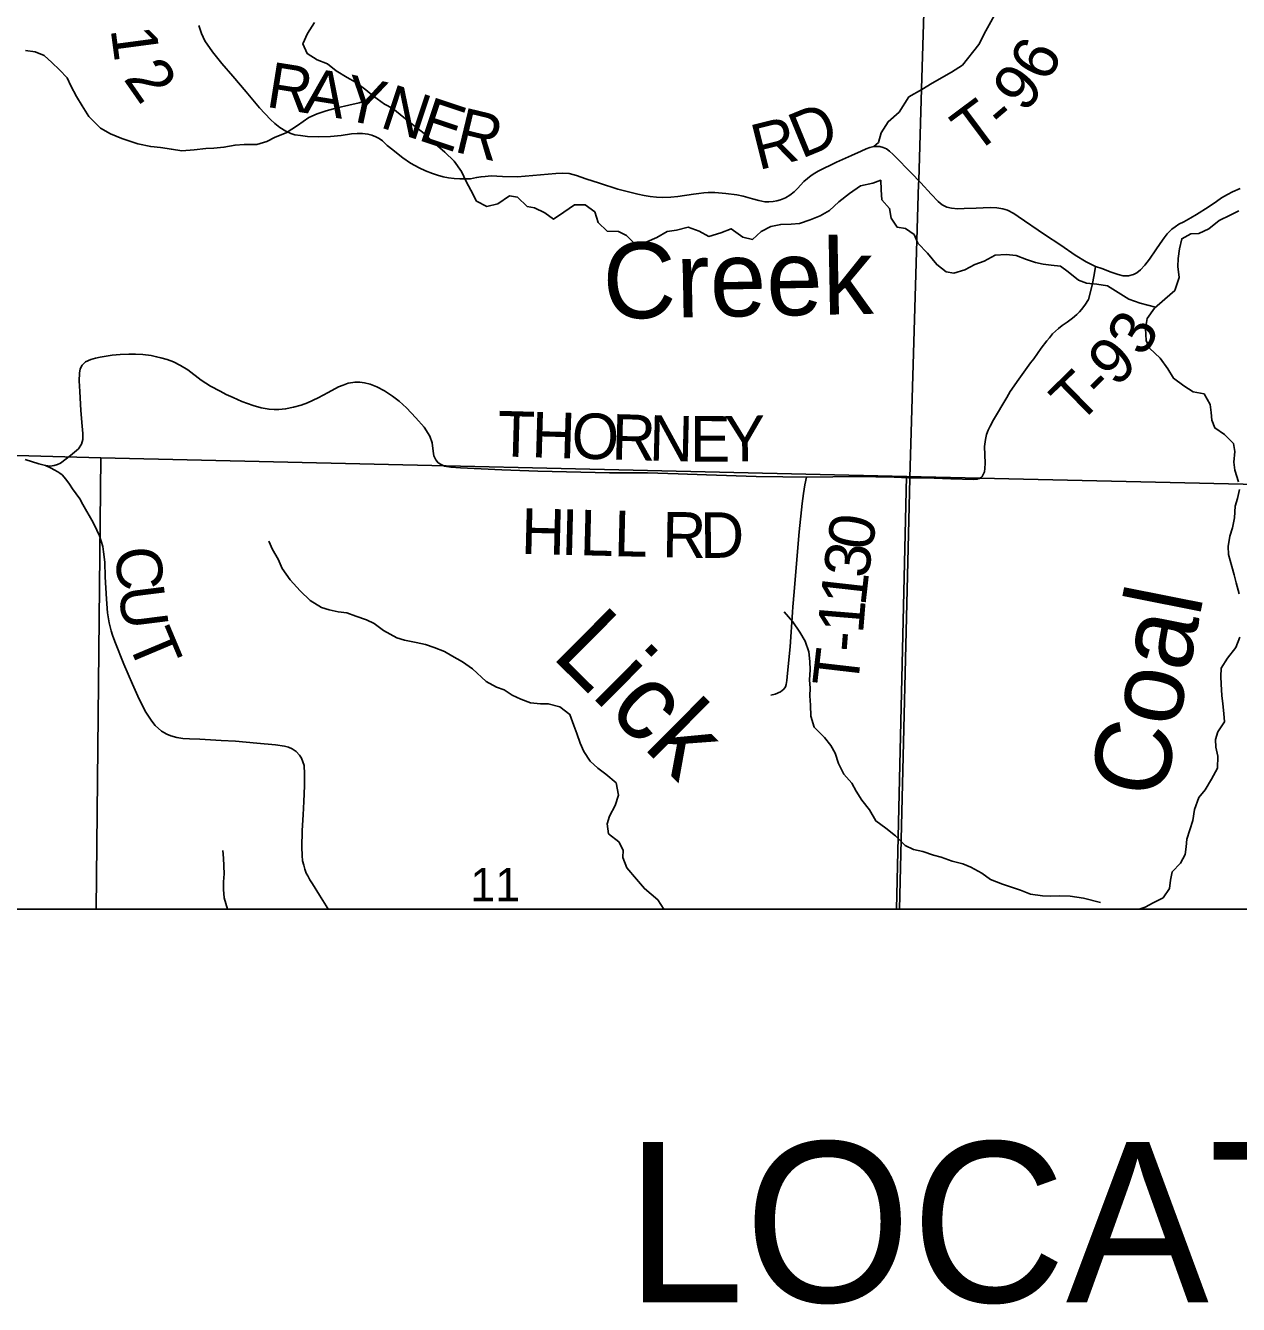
# Model space of a CAD drawing. Extents: x 0 to 34, y 0 to 22.
# Drawn here: x 2.631 to 4.145, y 14.08 to 15.676 of the extents above; entities that cross this region are included whole.
import ezdxf

# ---------------------------------------------------------------- set-up
doc = ezdxf.new("R2010")
doc.units = 0
for name, color, linetype in [('GM_X_Corporation', 7, 'Continuous'), ('GM_X_County_Road', 7, 'Continuous'), ('GM_X_County_Road_Text', 7, 'Continuous'), ('GM_X_Minor_River', 7, 'Continuous'), ('GM_X_Minor_River_Text', 7, 'Continuous'), ('GM_X_Section_Text', 7, 'Continuous'), ('GM_X_Township_Road', 7, 'Continuous'), ('GM_X_Township_Road_Text', 7, 'Continuous'), ('SH_Text', 7, 'Continuous')]:
    doc.layers.add(name, color=color, linetype=linetype)

msp = doc.modelspace()

# ---------------------------------------------------------------- linework, layer by layer
at = {"layer": 'GM_X_Corporation'}
for points in [[(4.1576, 16.1007), (3.7652, 16.1115), (2.3935, 16.1523), (2.3716, 16.1532), (1.6311, 16.1731), (1.6311, 14.5734), (8.4311, 14.5734)], [(4.1576, 16.1007), (3.7652, 16.1115), (3.7495, 15.5967), (3.7461, 15.4826), (3.7459, 15.4785), (3.7348, 15.1121), (3.7347, 15.1105), (3.7221, 14.5734), (8.4311, 14.5734)]]:
    msp.add_lwpolyline(points, dxfattribs=at)
for points in [[(1.6311, 16.1731), (1.6311, 14.5734), (3.7221, 14.5734), (3.7347, 15.1105), (3.7348, 15.1121), (3.7459, 15.4785), (3.7461, 15.4826), (3.7495, 15.5967), (3.7652, 16.1115), (2.3935, 16.1523), (2.3716, 16.1532)], [(1.7122, 14.5734), (2.7191, 14.5734), (2.725, 15.1366), (1.7214, 15.1643)], [(2.7191, 14.5734), (3.7181, 14.5734), (3.7309, 15.1133), (2.725, 15.1366)], [(3.7181, 14.5734), (4.7275, 14.5734), (4.7356, 15.0283), (4.7361, 15.0901), (3.7309, 15.1133)]]:
    msp.add_lwpolyline(points, close=True, dxfattribs=at)
at = {"layer": 'GM_X_County_Road'}
for points in [[(2.8476, 15.676), (2.8508, 15.6658), (2.8549, 15.6566), (2.8644, 15.6432), (2.8761, 15.6287), (2.8897, 15.6126), (2.9066, 15.5932), (2.9231, 15.5733), (2.9368, 15.5588), (2.9423, 15.5537), (2.9485, 15.5485), (2.9561, 15.544), (2.9622, 15.5411), (2.9671, 15.5397), (2.9745, 15.5386), (2.983, 15.5376), (2.9973, 15.5371), (3.0117, 15.5375), (3.0252, 15.5388), (3.0381, 15.5406), (3.0449, 15.5411), (3.0518, 15.5413), (3.0585, 15.5405), (3.0634, 15.5392), (3.0683, 15.5371), (3.0726, 15.5348), (3.0766, 15.532), (3.0827, 15.5264), (3.0897, 15.5206), (3.0961, 15.5153), (3.1022, 15.5107), (3.1118, 15.5043), (3.1226, 15.4985), (3.1305, 15.4946), (3.1389, 15.4913), (3.1452, 15.4892), (3.1523, 15.4873), (3.1592, 15.486), (3.1661, 15.485), (3.1734, 15.4845), (3.1798, 15.4845), (3.1865, 15.4848), (3.1941, 15.4862), (3.1997, 15.4873), (3.205, 15.4877), (3.2124, 15.4882), (3.2193, 15.488), (3.2265, 15.4876), (3.245, 15.4871), (3.2929, 15.4914), (3.3011, 15.4917), (3.3097, 15.4912), (3.3187, 15.4887), (3.3303, 15.4847), (3.3477, 15.479), (3.3705, 15.4719), (3.3822, 15.4688), (3.3954, 15.4656), (3.4032, 15.464), (3.4108, 15.4627), (3.4185, 15.4616), (3.4267, 15.4614), (3.4364, 15.4616), (3.4453, 15.4624), (3.4648, 15.4655), (3.4714, 15.4665), (3.4777, 15.4671), (3.4833, 15.4675), (3.4917, 15.4677), (3.5054, 15.4665), (3.519, 15.4646), (3.5269, 15.4628), (3.5386, 15.4596), (3.5463, 15.4576), (3.554, 15.456), (3.5588, 15.456), (3.5645, 15.4564), (3.5687, 15.4572), (3.5733, 15.4584), (3.5795, 15.461), (3.5852, 15.4644), (3.5904, 15.4684), (3.5948, 15.4725), (3.6027, 15.4811), (3.6118, 15.4887), (3.6163, 15.4917), (3.6206, 15.4941), (3.6434, 15.5052), (3.662, 15.5139), (3.674, 15.5193), (3.6804, 15.5221)], [(3.6804, 15.5221), (3.685, 15.5238), (3.6899, 15.5249), (3.6976, 15.5249), (3.7016, 15.5239), (3.7059, 15.5219), (3.7097, 15.5192), (3.7141, 15.5151), (3.7386, 15.4899), (3.7463, 15.4821), (3.7487, 15.4796), (3.7615, 15.4653), (3.7701, 15.4562), (3.7753, 15.4523), (3.7811, 15.4494), (3.787, 15.4478), (3.7948, 15.4472), (3.8026, 15.4474), (3.8176, 15.4481), (3.8353, 15.4488), (3.8435, 15.4483), (3.8511, 15.4471), (3.8567, 15.4454), (3.8645, 15.4413), (3.8703, 15.4374), (3.9031, 15.4152), (3.9234, 15.4017), (3.9412, 15.3893), (3.9551, 15.3811), (3.9668, 15.3752), (3.9746, 15.3726), (3.9864, 15.368), (3.9951, 15.3652), (4.0013, 15.3637), (4.0079, 15.3636), (4.0142, 15.3651), (4.0184, 15.3675), (4.023, 15.371), (4.0284, 15.3769), (4.0339, 15.3844), (4.0421, 15.3959), (4.0475, 15.4039), (4.0524, 15.4109), (4.0563, 15.4158), (4.0621, 15.4216), (4.066, 15.4247), (4.0708, 15.4279), (4.0767, 15.4311), (4.0855, 15.4358), (4.0929, 15.4403), (4.1072, 15.4491), (4.1178, 15.4565), (4.124, 15.4608), (4.1314, 15.4652), (4.1377, 15.4684), (4.1474, 15.4727)]]:
    msp.add_lwpolyline(points, dxfattribs=at)
at = {"layer": 'GM_X_Minor_River'}
for points in [[(4.0414, 15.3243), (4.0224, 15.3296), (4.0083, 15.3345), (3.9818, 15.3511), (3.9685, 15.3533), (3.9553, 15.3544), (3.9454, 15.3582), (3.9325, 15.3684), (3.923, 15.3755), (3.9113, 15.377), (3.9014, 15.3781), (3.8916, 15.3804), (3.8806, 15.3841), (3.8677, 15.389), (3.8552, 15.3901), (3.8416, 15.3893), (3.8276, 15.382), (3.8162, 15.3778), (3.8034, 15.371), (3.7898, 15.3671), (3.7803, 15.3686), (3.7685, 15.3777), (3.7571, 15.3917), (3.745, 15.4045), (3.7404, 15.4151), (3.7294, 15.4227), (3.7192, 15.4241), (3.7116, 15.4355), (3.7096, 15.4476), (3.7001, 15.4582), (3.6993, 15.4707), (3.6985, 15.4828), (3.6887, 15.479), (3.6732, 15.4759), (3.6596, 15.4664), (3.6464, 15.4561), (3.6347, 15.4451), (3.6229, 15.4386), (3.6105, 15.4336), (3.5972, 15.429), (3.5866, 15.4282), (3.5738, 15.4278), (3.5616, 15.4251), (3.5495, 15.419), (3.5386, 15.4091), (3.5265, 15.4117), (3.5117, 15.4223), (3.4988, 15.4173), (3.4841, 15.4127), (3.4719, 15.4191), (3.4583, 15.4244), (3.4435, 15.4205), (3.4318, 15.419), (3.4193, 15.4114), (3.4065, 15.406), (3.3921, 15.4029), (3.3811, 15.4139), (3.3712, 15.4188), (3.3572, 15.4195), (3.3458, 15.4301), (3.3416, 15.4433), (3.3295, 15.452), (3.3162, 15.4523), (3.303, 15.4432), (3.2901, 15.4344), (3.2791, 15.442), (3.2666, 15.4484), (3.2571, 15.4502), (3.245, 15.4616), (3.2351, 15.4634), (3.2208, 15.4532), (3.2068, 15.4501), (3.1939, 15.4569), (3.187, 15.4705), (3.181, 15.4811), (3.1752, 15.4936), (3.1661, 15.5068), (3.1543, 15.5178), (3.1426, 15.5283), (3.1285, 15.5412), (3.1156, 15.551), (3.1031, 15.5612), (3.0894, 15.5725), (3.0792, 15.5778), (3.0655, 15.5876), (3.0557, 15.5955), (3.0431, 15.6053), (3.0325, 15.611), (3.0189, 15.6193), (3.0079, 15.6283), (2.995, 15.6332), (2.9828, 15.6408), (2.9771, 15.6529), (2.9831, 15.6658), (2.9918, 15.6798)], [(3.0673, 15.5863), (3.0474, 15.5796), (3.0345, 15.5765), (3.0201, 15.5734), (3.0065, 15.5696), (2.9952, 15.5657), (2.9846, 15.5612), (2.9706, 15.5513), (2.9566, 15.5421), (2.9426, 15.5364), (2.9324, 15.531), (2.9199, 15.5276), (2.904, 15.5275), (2.8927, 15.5267), (2.8787, 15.524), (2.8662, 15.5228), (2.856, 15.5224), (2.8416, 15.5209), (2.8264, 15.5197), (2.8132, 15.5215), (2.7995, 15.5238), (2.7874, 15.5248), (2.7711, 15.5282), (2.7514, 15.535), (2.737, 15.5406), (2.7245, 15.5478), (2.7101, 15.5625), (2.7017, 15.5757), (2.6948, 15.5875), (2.6876, 15.6007), (2.683, 15.6106), (2.6735, 15.6208), (2.6641, 15.6298), (2.6542, 15.6385), (2.6432, 15.643), (2.6311, 15.6449)], [(4.1454, 15.4445), (4.1349, 15.4392), (4.1209, 15.4327), (4.108, 15.4224), (4.0955, 15.4163), (4.0857, 15.4159), (4.0744, 15.4098), (4.0714, 15.3973), (4.0699, 15.3851), (4.0695, 15.3753), (4.0711, 15.3616), (4.0655, 15.3453), (4.053, 15.3343), (4.0402, 15.3232), (4.0311, 15.3103), (4.0289, 15.2978), (4.0297, 15.283), (4.0339, 15.2732), (4.0472, 15.2607), (4.0571, 15.2474), (4.0639, 15.2357), (4.0768, 15.2263), (4.0886, 15.2187), (4.1022, 15.2165), (4.1098, 15.2029), (4.111, 15.193), (4.1118, 15.1836), (4.1156, 15.1737), (4.1277, 15.1654), (4.1387, 15.1544), (4.1407, 15.1442), (4.1392, 15.1309), (4.1404, 15.1211), (4.1453, 15.1067)], [(4.1465, 15.0968), (4.1439, 15.0858), (4.1409, 15.0763), (4.1402, 15.0615), (4.1375, 15.049), (4.1345, 15.0388), (4.1323, 15.0259), (4.1327, 15.016), (4.1369, 15.0009), (4.1396, 14.9903), (4.1423, 14.9804), (4.1461, 14.9668)], [(3.4277, 14.5734), (3.4203, 14.585), (3.4036, 14.599), (3.3937, 14.6107), (3.3816, 14.6247), (3.3766, 14.6376), (3.377, 14.6471), (3.3716, 14.6573), (3.3587, 14.6675), (3.3572, 14.6796), (3.3602, 14.6895), (3.3669, 14.7028), (3.3714, 14.7157), (3.3684, 14.7309), (3.3555, 14.7418), (3.3456, 14.7494), (3.3357, 14.7581), (3.3281, 14.7702), (3.3235, 14.7804), (3.3193, 14.7925), (3.3155, 14.8024), (3.3106, 14.8164), (3.298, 14.8258), (3.2836, 14.8296), (3.2738, 14.8295), (3.2613, 14.8306), (3.2495, 14.8355), (3.2385, 14.8404), (3.2287, 14.8468), (3.2188, 14.8502), (3.2059, 14.8574), (3.1892, 14.8733), (3.1767, 14.8819), (3.1634, 14.8895), (3.1539, 14.8948), (3.141, 14.9), (3.1304, 14.9034), (3.1187, 14.906), (3.1043, 14.909), (3.0944, 14.912), (3.0778, 14.921), (3.0664, 14.9297), (3.0569, 14.9342), (3.0432, 14.9391), (3.0323, 14.9429), (3.0213, 14.9444), (3.0103, 14.9466), (3.0004, 14.9496), (2.9864, 14.9583), (2.9739, 14.9707), (2.9613, 14.9844), (2.9514, 14.9984), (2.9465, 15.0101), (2.9392, 15.0222), (2.9347, 15.0324)], [(3.9728, 14.5816), (3.9515, 14.5872), (3.9352, 14.5894), (3.922, 14.5898), (3.911, 14.5897), (3.9004, 14.5901), (3.8856, 14.5919), (3.8731, 14.5972), (3.8606, 14.6013), (3.8504, 14.6043), (3.8356, 14.6103), (3.8246, 14.6183), (3.8109, 14.6258), (3.8011, 14.6299), (3.7878, 14.6333), (3.7738, 14.6382), (3.7643, 14.6408), (3.751, 14.6453), (3.7393, 14.6476), (3.7291, 14.6528), (3.7169, 14.6646), (3.7051, 14.6744), (3.6926, 14.6834), (3.6846, 14.6971), (3.6751, 14.7095), (3.6679, 14.7205), (3.6626, 14.7304), (3.6527, 14.7417), (3.6458, 14.755), (3.6416, 14.7678), (3.6363, 14.7777), (3.6283, 14.7875), (3.6154, 14.8004), (3.6112, 14.814), (3.6108, 14.8277), (3.61, 14.8394), (3.6103, 14.8489), (3.6095, 14.8595), (3.6103, 14.872), (3.6099, 14.8823), (3.6087, 14.8944), (3.6041, 14.9077), (3.5976, 14.919), (3.5889, 14.9319), (3.5782, 14.9444)], [(4.1467, 14.9125), (4.1418, 14.8996), (4.1316, 14.8863), (4.1233, 14.8741), (4.123, 14.8635), (4.1234, 14.854), (4.1245, 14.84), (4.1257, 14.8294), (4.1269, 14.8173), (4.1277, 14.807), (4.1194, 14.7945), (4.1164, 14.785), (4.1168, 14.7755), (4.1195, 14.7642), (4.1191, 14.7494), (4.1116, 14.7357), (4.1037, 14.722), (4.0958, 14.7125), (4.0901, 14.6977)], [(4.0901, 14.6977), (4.0883, 14.684), (4.0842, 14.6722), (4.0808, 14.6605), (4.0797, 14.651), (4.0786, 14.6415), (4.0726, 14.6309), (4.0624, 14.6198), (4.0601, 14.6096), (4.059, 14.599), (4.0511, 14.5876), (4.0386, 14.5814), (4.0288, 14.5757), (4.0211, 14.5734)], [(2.883, 14.5734), (2.8789, 14.5873), (2.8781, 14.598), (2.8784, 14.6074), (2.8791, 14.6173), (2.8783, 14.637), (2.8772, 14.6465)]]:
    msp.add_lwpolyline(points, dxfattribs=at)
at = {"layer": 'GM_X_Township_Road'}
for points in [[(3.6899, 15.5249), (3.6958, 15.5301), (3.6992, 15.5421), (3.7078, 15.5559), (3.7216, 15.5679), (3.7336, 15.5868), (3.7497, 15.5961), (3.7628, 15.604), (3.7869, 15.6177), (3.8006, 15.6263), (3.8212, 15.6521), (3.8298, 15.6693), (3.847, 15.7002)], [(3.9668, 15.3752), (3.9649, 15.365), (3.9625, 15.3518), (3.9577, 15.3341), (3.9533, 15.3269), (3.9493, 15.3214), (3.9468, 15.3185), (3.9434, 15.3152), (3.9378, 15.3106), (3.9312, 15.3059), (3.9252, 15.3016), (3.9206, 15.2978), (3.913, 15.291), (3.9094, 15.2864), (3.9057, 15.2825), (3.899, 15.2734), (3.8897, 15.2602), (3.8855, 15.2548), (3.871, 15.2346), (3.8603, 15.2192), (3.856, 15.2119), (3.8392, 15.1838), (3.8353, 15.1761), (3.8328, 15.171), (3.8305, 15.1657), (3.8292, 15.1594), (3.8283, 15.1505), (3.8288, 15.13), (3.8285, 15.1233), (3.828, 15.1188), (3.8266, 15.1156), (3.8251, 15.1133), (3.8239, 15.1119), (3.8218, 15.1108), (3.8209, 15.1105)], [(3.7331, 15.1116), (3.7152, 15.1122), (3.6924, 15.1127), (3.6676, 15.113), (3.6386, 15.1127), (3.606, 15.1122), (3.5762, 15.1126), (3.5432, 15.1133), (3.4812, 15.1154), (3.4457, 15.1167), (3.4074, 15.1177), (3.3602, 15.1178), (3.2707, 15.1198), (3.2258, 15.1216), (3.174, 15.1238), (3.1621, 15.1247), (3.1541, 15.1261), (3.15, 15.128), (3.146, 15.1304), (3.1432, 15.1341), (3.1408, 15.139), (3.1399, 15.1449), (3.1385, 15.1552), (3.1356, 15.1634), (3.1285, 15.1746), (3.1181, 15.1865), (3.1065, 15.1989), (3.0973, 15.2072), (3.0893, 15.2134), (3.0793, 15.2201), (3.0696, 15.225), (3.0612, 15.2284), (3.0543, 15.23), (3.0483, 15.2308), (3.0424, 15.2309), (3.034, 15.2295), (3.0274, 15.2273), (3.0217, 15.2249), (3.0089, 15.2179), (2.9964, 15.2114), (2.9832, 15.2052), (2.975, 15.202), (2.9657, 15.1996), (2.9558, 15.1975), (2.9474, 15.1966), (2.9416, 15.1967), (2.935, 15.1971), (2.9254, 15.1989), (2.9152, 15.2016), (2.9011, 15.2069), (2.8902, 15.2116), (2.8816, 15.2156), (2.8739, 15.2196), (2.8621, 15.2257), (2.8502, 15.2335), (2.8336, 15.2464), (2.8247, 15.2518), (2.8156, 15.2561), (2.8078, 15.259), (2.8, 15.2613), (2.7946, 15.2627), (2.7879, 15.264), (2.7774, 15.2654), (2.7685, 15.2658), (2.7602, 15.2658), (2.7491, 15.2652), (2.7393, 15.2644), (2.7244, 15.262), (2.7183, 15.2609), (2.7126, 15.2591), (2.7061, 15.2562), (2.7018, 15.2523), (2.6995, 15.2474), (2.6983, 15.2422), (2.6982, 15.2326), (2.6987, 15.2193), (2.7001, 15.1954), (2.7018, 15.176), (2.7025, 15.167), (2.7026, 15.1595), (2.7009, 15.1536), (2.6973, 15.1479), (2.6872, 15.1394), (2.6749, 15.1299), (2.6709, 15.1281), (2.6668, 15.1268), (2.6619, 15.126), (2.6559, 15.1267)], [(3.009, 14.5734), (3.0064, 14.5774), (2.9981, 14.5907), (2.9893, 14.6048), (2.9859, 14.6101), (2.9833, 14.6149), (2.9815, 14.6182), (2.9797, 14.6232), (2.9783, 14.628), (2.977, 14.6338), (2.9762, 14.6403), (2.9759, 14.6508), (2.9766, 14.6711), (2.9774, 14.6848), (2.9777, 14.6912), (2.9784, 14.7076), (2.9792, 14.727), (2.9794, 14.7423), (2.9787, 14.7526), (2.9756, 14.7617), (2.9731, 14.7654), (2.9689, 14.77), (2.9639, 14.7733), (2.9592, 14.7754), (2.9544, 14.7766), (2.943, 14.7784), (2.9198, 14.7804), (2.8933, 14.7828), (2.8753, 14.7839), (2.8485, 14.7853), (2.8359, 14.7858), (2.8273, 14.7863), (2.8199, 14.7874), (2.8125, 14.7895), (2.8074, 14.7916), (2.8008, 14.7956), (2.7929, 14.8025), (2.7888, 14.8079), (2.7814, 14.8193), (2.7731, 14.8354), (2.7645, 14.8541), (2.754, 14.8792), (2.7426, 14.9073), (2.7398, 14.9152), (2.738, 14.9205), (2.7354, 14.9305), (2.7336, 14.9431), (2.7323, 14.9603), (2.7303, 14.9879), (2.73, 15.0061), (2.7285, 15.0191), (2.7275, 15.0257), (2.7255, 15.0326), (2.7233, 15.0391), (2.7201, 15.0462), (2.7154, 15.0559), (2.7025, 15.0783), (2.6987, 15.0851), (2.6898, 15.0976), (2.686, 15.1036), (2.6815, 15.1097), (2.6767, 15.1154), (2.674, 15.1174), (2.6714, 15.1189), (2.667, 15.1213), (2.6629, 15.1236), (2.6559, 15.1267), (2.6477, 15.1291), (2.6305, 15.1342)], [(3.5614, 14.8404), (3.5669, 14.8417), (3.5735, 14.8445), (3.5777, 14.848), (3.5795, 14.8506), (3.5807, 14.8536), (3.5814, 14.8588), (3.582, 14.8676), (3.5854, 14.9006), (3.5883, 14.944), (3.5889, 14.9506), (3.5904, 14.9691), (3.5944, 15.0146), (3.5969, 15.0441), (3.6006, 15.0793), (3.602, 15.0918), (3.6038, 15.1028), (3.606, 15.1122)], [(3.8209, 15.1105), (3.8191, 15.11), (3.8147, 15.1093), (3.7862, 15.1102), (3.7654, 15.1109), (3.735, 15.1116), (3.7331, 15.1116)]]:
    msp.add_lwpolyline(points, dxfattribs=at)
at = {"layer": 'SH_Text'}
msp.add_line((8.4311, 14.5734), (1.6311, 14.5734), dxfattribs=at)

# ---------------------------------------------------------------- texts
at = {"layer": 'GM_X_County_Road_Text'}
for s, rotation, p in [('1', 277.6209, (2.7372, 15.6715)), ('2', 304.9441, (2.7525, 15.6095)), ('R', 350.9702, (2.93, 15.5747)), ('A', 350.9467, (2.9761, 15.5674)), ('Y', 347.8142, (3.0246, 15.5596)), ('N', 341.58, (3.0719, 15.5495)), ('E', 341.5325, (3.1194, 15.5337)), ('D', 22.3965, (3.5995, 15.5093)), ('R', 346.4844, (3.1648, 15.5188)), ('R', 14.0107, (3.5458, 15.4952))]:
    msp.add_text(s, height=0.0568, rotation=rotation, dxfattribs=at).set_placement(p)
at = {"layer": 'GM_X_Minor_River_Text'}
for s, height, rotation, p in [('Creek', 0.09469, 1.089, (3.3524, 15.3098)), ('Coal', 0.09473, 78.7779, (4.0512, 14.7084)), ('Lick', 0.09472, 315.2143, (3.2862, 14.889))]:
    msp.add_text(s, height=height, rotation=rotation, dxfattribs=at).set_placement(p)
at = {"layer": 'GM_X_Section_Text'}
msp.add_text('11', height=0.04186, rotation=0, dxfattribs=at).set_placement((3.1862, 14.5829))
at = {"layer": 'GM_X_Township_Road_Text'}
for s, rotation, p in [('6', 62.5332, (3.907, 15.603)), ('9', 50.9626, (3.8781, 15.5654)), ('T', 36.707, (3.8151, 15.5143)), ('-', 40.2825, (3.8522, 15.5421)), ('3', 60.1136, (4.0268, 15.2607)), ('9', 45.1805, (3.9924, 15.2231)), ('T', 44.3242, (3.9447, 15.1764)), ('-', 44.47, (3.9752, 15.2062)), ('T', 358.367, (3.2196, 15.1384)), ('H', 358.3673, (3.2621, 15.1372)), ('O', 358.3678, (3.3121, 15.1358)), ('R', 358.3679, (3.3621, 15.1344)), ('N', 358.5681, (3.409, 15.1331)), ('E', 359.8052, (3.4603, 15.1318)), ('Y', 1.0853, (3.5042, 15.1317)), ('H', 358.5464, (3.2491, 15.0168)), ('I', 358.548, (3.2991, 15.0156)), ('L', 358.5511, (3.3224, 15.015)), ('L', 358.5965, (3.365, 15.0139)), ('R', 358.9854, (3.4254, 15.0124)), ('D', 0.2036, (3.4733, 15.0116)), ('0', 80.7225, (3.6873, 15.0193)), ('C', 274.4421, (2.7429, 15.0238)), ('3', 83.1299, (3.6832, 14.9852)), ('1', 83.5753, (3.6793, 14.9505)), ('U', 277.2318, (2.7468, 14.9742)), ('1', 85.2904, (3.6764, 14.9161)), ('T', 292.8112, (2.7575, 14.9084)), ('-', 85.495, (3.6746, 14.8929)), ('T', 83.3943, (3.6695, 14.8484))]:
    msp.add_text(s, height=0.0568, rotation=rotation, dxfattribs=at).set_placement(p)
at = {"layer": 'SH_Text'}
msp.add_text('LOCATION MAP', height=0.2, dxfattribs=at).set_placement((3.3798, 14.0829))

doc.saveas('drawing.dxf')
